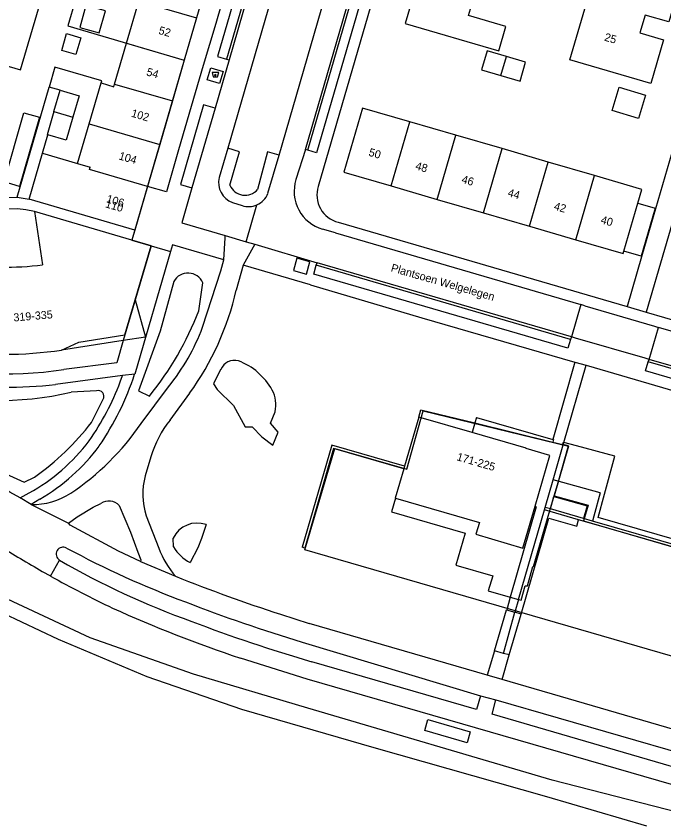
# Model space of a CAD drawing. Extents: x 194485 to 197793, y 468269 to 470822.
# Drawn here: x 194901 to 194998.1, y 469620.1 to 469740.5 of the extents above; entities that cross this region are included whole.
import ezdxf

# ---------------------------------------------------------------- set-up
doc = ezdxf.new("R2010")
doc.units = 0
for name, color, linetype in [('BGT begrenzing pand op maaiveld onder overbouw', 7, 'Continuous'), ('BGT grensvlak begroeid terreindeel', 7, 'Continuous'), ('BGT grensvlak begroeid terreindeel LR', 7, 'Continuous'), ('BGT grensvlak gebouwinstallatie plus 1', 7, 'Continuous'), ('BGT grensvlak onbegroeid terreindeel', 7, 'Continuous'), ('BGT grensvlak onbegroeid terreindeel LR', 7, 'Continuous'), ('BGT grensvlak ondersteunend wegdeel', 7, 'Continuous'), ('BGT grensvlak overig bouwwerk', 7, 'Continuous'), ('BGT grensvlak overig bouwwerk uitbreiding populatie', 7, 'Continuous'), ('BGT grensvlak pand deel overbouw', 7, 'Continuous'), ('BGT grensvlak pand min 1', 7, 'Continuous'), ('BGT grensvlak pand op maaiveld', 7, 'Continuous'), ('BGT grensvlak pand op maaiveld LR', 7, 'Continuous'), ('BGT grensvlak scheiding', 7, 'Continuous'), ('BGT grensvlak waterdeel', 7, 'Continuous'), ('BGT grensvlak wegdeel', 7, 'Continuous'), ('BGT puntobject bak afval apart plaats', 7, 'Continuous'), ('BGT tekst huisnummerreeks', 7, 'Continuous'), ('BGT tekst huisnummerreeks min 1', 7, 'Continuous'), ('BGT tekst openbare ruimte label weg', 7, 'Continuous')]:
    doc.layers.add(name, color=color, linetype=linetype)

msp = doc.modelspace()

# ---------------------------------------------------------------- linework, layer by layer
at = {"layer": 'BGT begrenzing pand op maaiveld onder overbouw'}
msp.add_line((194917.33, 469692.72), (194918.86, 469697.98), dxfattribs=at)
for points in [[(194907.85, 469690.46), (194910.41, 469691.65), (194917.33, 469692.72)], [(194969.35, 469678.09), (194961.73, 469680.3), (194961.73, 469680.28), (194961.34, 469680.39)], [(194978.76, 469667.05), (194980.96, 469674.66), (194977.41, 469675.69), (194977.42, 469675.75), (194969.35, 469678.09)], [(194957.86, 469668.27), (194970.42, 469664.64), (194969.89, 469662.85), (194976.95, 469660.79), (194978.76, 469667.05)]]:
    msp.add_lwpolyline(points, dxfattribs=at)
at = {"layer": 'BGT grensvlak begroeid terreindeel'}
for p, q in [((194928.38, 469696.35), (194929, 469700.54)), ((194913.06, 469684.35), (194909.3, 469684.14)), ((194912.33, 469679.62), (194914.05, 469683.08)), ((194924.63, 469660.97), (194924.55, 469662.26))]:
    msp.add_line(p, q, dxfattribs=at)
for points in [[(194924.66, 469700.75), (194922.59, 469693.27), (194919.34, 469684.37), (194921, 469683.57)], [(194931.67, 469687.54), (194930.59, 469685.41), (194931.17, 469684.54), (194933.58, 469682.13), (194935.32, 469678.95), (194936.4, 469678.95), (194937.82, 469677.44), (194939.49, 469676.21), (194940.3, 469678.14), (194939.15, 469679.49), (194939.82, 469681.21)], [(194880.81, 469682.3), (194889.88, 469677.07), (194897.14, 469672.94), (194902.24, 469670.67), (194903.78, 469671.41)], [(194929.49, 469664.31), (194928.78, 469662.22), (194928.23, 469660.82), (194927.09, 469658.65)]]:
    msp.add_lwpolyline(points, dxfattribs=at)
for centre, radius, start, end in [((194926.78, 469699.56), 2.43, 23.9013, 150.6072), ((194885.11, 469712.8), 46.29, 320.8368, 339.1911), ((194933.76, 469686.66), 2.26, 75.4097, 157.1488), ((194930.81, 469679.68), 9.82, 29.1576, 69.0085), ((194898.54, 469731.09), 48.17, 254.6702, 282.906), ((194913.32, 469683.53), 0.862, 328.322, 107.5462), ((194935.4, 469682.28), 4.54, 346.3659, 28.8095), ((194881.04, 469703.67), 39.47, 305.1859, 322.463), ((194928.16, 469660.55), 3.99, 70.4359, 154.6193), ((194929.58, 469663.75), 5.68, 209.3541, 244.023)]:
    msp.add_arc(centre, radius, start, end, dxfattribs=at)
at = {"layer": 'BGT grensvlak begroeid terreindeel LR'}
msp.add_lwpolyline([(195139.42, 469572.39), (195126.11, 469578.61), (195110.6, 469585.25), (195087.07, 469594.31), (195079.56, 469596.73), (195063.35, 469601.44), (195045.76, 469607.19), (195000.41, 469621.1), (194981.32, 469626.01), (194944.75, 469636.79), (194927.61, 469641.91), (194912.14, 469647.34), (194895.12, 469655.28), (194890.12, 469657.98)], dxfattribs=at)
at = {"layer": 'BGT grensvlak gebouwinstallatie plus 1'}
for p, q in [((194977.35, 469733.59), (194974.47, 469734.43)), ((194976.53, 469730.76), (194977.35, 469733.59)), ((194973.64, 469731.6), (194976.53, 469730.76)), ((194899.23, 469715.64), (194902.21, 469726.02)), ((194904.52, 469725.35), (194901.53, 469714.98)), ((194902.21, 469726.02), (194904.52, 469725.35)), ((194901.53, 469714.98), (194899.23, 469715.64))]:
    msp.add_line(p, q, dxfattribs=at)
for points in [[(194991.36, 469729.84), (194995.33, 469728.62), (194994.27, 469725.13), (194990.3, 469726.34), (194991.36, 469729.84)], [(194994.16, 469712.47), (194996.77, 469711.71), (194994.68, 469704.52), (194992.07, 469705.28)]]:
    msp.add_lwpolyline(points, dxfattribs=at)
at = {"layer": 'BGT grensvlak onbegroeid terreindeel'}
msp.add_lwpolyline([(194962.25, 469633.46), (194962.72, 469635.09), (194969.06, 469633.26), (194968.59, 469631.62), (194962.25, 469633.46)], dxfattribs=at)
at = {"layer": 'BGT grensvlak onbegroeid terreindeel LR'}
msp.add_lwpolyline([(194913.76, 469730.48), (194913.85, 469730.79), (194906.83, 469732.83), (194905.98, 469729.84)], dxfattribs=at)
at = {"layer": 'BGT grensvlak ondersteunend wegdeel'}
for points in [[(194933.05, 469715.15), (194934.51, 469720.17), (194932.73, 469720.69)], [(194940.41, 469719.68), (194938.67, 469720.14), (194937.19, 469714.51)]]:
    msp.add_lwpolyline(points, dxfattribs=at)
msp.add_arc((194935.32, 469716.11), 2.46, 202.9234, 319.4844, dxfattribs=at)
at = {"layer": 'BGT grensvlak overig bouwwerk'}
msp.add_lwpolyline([(194943.1, 469704.22), (194942.56, 469702.38), (194944.51, 469701.82), (194945.04, 469703.66), (194943.1, 469704.22)], dxfattribs=at)
at = {"layer": 'BGT grensvlak overig bouwwerk uitbreiding populatie'}
for p, q in [((194907.87, 469735.34), (194908.6, 469737.87)), ((194908.6, 469737.87), (194910.73, 469737.25)), ((194910.73, 469737.25), (194909.99, 469734.72)), ((194909.99, 469734.72), (194907.87, 469735.34)), ((194971.58, 469735.27), (194970.76, 469732.44)), ((194974.47, 469734.43), (194971.58, 469735.27)), ((194973.64, 469731.6), (194974.47, 469734.43)), ((194970.76, 469732.44), (194973.64, 469731.6))]:
    msp.add_line(p, q, dxfattribs=at)
at = {"layer": 'BGT grensvlak pand deel overbouw'}
for p, q in [((194917.08, 469691.9), (194907.85, 469690.46)), ((194969.76, 469679.53), (194981.43, 469676.68)), ((194981.43, 469676.68), (194982.91, 469676.32)), ((194980.98, 469666.41), (194982.21, 469670.63)), ((194975.06, 469653.44), (194976.3, 469653.09))]:
    msp.add_line(p, q, dxfattribs=at)
for points in [[(194918.86, 469697.98), (194920.4, 469692.41), (194917.08, 469691.9)], [(194961.34, 469680.39), (194961.65, 469681.5), (194969.76, 469679.53)], [(194982.21, 469670.63), (194983.8, 469676.1), (194982.91, 469676.32)], [(194957.86, 469668.27), (194957.28, 469666.24), (194968.29, 469663.02), (194966.89, 469658.25), (194972.42, 469656.64), (194971.76, 469654.39), (194975.06, 469653.44)], [(194976.3, 469653.09), (194976.69, 469652.98), (194977.3, 469655.15), (194977.62, 469655.14), (194978.45, 469658.05), (194978.55, 469658.03), (194980.98, 469666.41)]]:
    msp.add_lwpolyline(points, dxfattribs=at)
at = {"layer": 'BGT grensvlak pand min 1'}
for points in [[(194861.26, 469761.31), (194911.07, 469746.86), (194908.8, 469739.04), (194926.21, 469733.91), (194918.38, 469706.93), (194921.25, 469706.09), (194917.08, 469691.9), (194907.85, 469690.46)], [(195087.8, 469618.92), (195038.21, 469633.32), (194995.61, 469645.66), (194944.3, 469660.52), (194948.77, 469675.69), (194959.55, 469672.6), (194962, 469681.35), (194983.77, 469676.04), (194981.65, 469668.62), (194986.71, 469667.21), (194986.04, 469664.86), (195014.94, 469656.43), (195017.52, 469665.35), (195039.43, 469659.92), (195037.27, 469652.55), (195042.33, 469651.11), (195041.68, 469648.74), (195070.6, 469640.31), (195073.09, 469649.05), (195078.94, 469647.69), (195095.05, 469643.75)]]:
    msp.add_lwpolyline(points, dxfattribs=at)
msp.add_arc((194899.31, 469747.45), 57.63, 261.3794, 278.5138, dxfattribs=at)
at = {"layer": 'BGT grensvlak pand op maaiveld'}
for p, q in [((194929.88, 469746.52), (194928.06, 469740.23)), ((194917.58, 469736.45), (194919.4, 469742.74)), ((194928.06, 469740.23), (194926.22, 469733.9)), ((194915.79, 469730.29), (194917.58, 469736.45)), ((194926.22, 469733.9), (194924.44, 469727.78)), ((194911.98, 469724.35), (194913.76, 469730.48)), ((194906.68, 469726.19), (194907.61, 469729.37)), ((194924.44, 469727.78), (194922.55, 469721.27)), ((194910.24, 469718.4), (194911.98, 469724.35)), ((194966.91, 469722.64), (194960, 469724.65)), ((194973.83, 469720.63), (194966.91, 469722.64)), ((194922.55, 469721.27), (194920.72, 469714.98)), ((194980.74, 469718.61), (194973.83, 469720.63)), ((194902.97, 469713.05), (194904.98, 469719.96)), ((194904.98, 469719.96), (194910.24, 469718.4)), ((194987.66, 469716.6), (194980.74, 469718.61)), ((194920.72, 469714.98), (194918.82, 469708.43)), ((194957.2, 469715.05), (194964.12, 469713.03)), ((194918.82, 469708.43), (194902.97, 469713.05)), ((194964.12, 469713.03), (194971.03, 469711.02)), ((194992.07, 469705.28), (194994.16, 469712.47)), ((194918.38, 469706.93), (194903.78, 469711.21)), ((194903.78, 469711.21), (194904.99, 469703.24)), ((194971.03, 469711.02), (194977.94, 469709.01)), ((194977.94, 469709.01), (194984.86, 469706.99)), ((194921.25, 469706.09), (194918.38, 469706.93)), ((194918.86, 469697.98), (194921.25, 469706.09)), ((194961.34, 469680.39), (194959.2, 469673.04)), ((194959.09, 469672.65), (194957.82, 469668.28)), ((194959.2, 469673.04), (194959.09, 469672.65)), ((194957.82, 469668.28), (194957.86, 469668.27))]:
    msp.add_line(p, q, dxfattribs=at)
for points in [[(194962.21, 469749.37), (194959.63, 469750.12), (194958.07, 469744.74), (194960.64, 469743.99), (194959.3, 469739.39), (194973.32, 469735.31), (194974.38, 469738.95), (194968.81, 469740.57), (194970.57, 469746.63)], [(194997.94, 469749.87), (194997.16, 469747.2), (195000.69, 469746.16), (194998.79, 469739.62), (194995.26, 469740.65)], [(194876.66, 469744.98), (194881.75, 469743.52), (194880.36, 469738.67), (194901.71, 469732.43), (194905.05, 469743.85), (194904.65, 469743.98), (194905.93, 469748.35)], [(194995.26, 469740.65), (194994.48, 469737.97), (194998.01, 469736.94), (194996.11, 469730.41), (194984, 469733.94), (194986.74, 469743.33)], [(194911.49, 469742.09), (194910.56, 469738.78), (194913.48, 469737.96), (194914.4, 469741.27), (194911.49, 469742.09)], [(194913.76, 469730.48), (194915.68, 469729.91), (194915.79, 469730.29)], [(194907.61, 469729.37), (194910.48, 469728.54), (194909.55, 469725.34)], [(194906.68, 469726.19), (194905.67, 469722.71), (194905.77, 469722.68)], [(194960, 469724.65), (194952.9, 469726.72), (194950.1, 469717.11), (194957.2, 469715.05)], [(194909.55, 469725.34), (194908.55, 469721.88), (194905.77, 469722.68)], [(194994.16, 469712.47), (194994.76, 469714.53), (194987.66, 469716.6)], [(194984.86, 469706.99), (194991.97, 469704.92), (194992.07, 469705.28)]]:
    msp.add_lwpolyline(points, dxfattribs=at)
for centre, radius, start, end in [((194899.21, 469746.36), 43.5, 261.2075, 277.6404), ((194899.31, 469747.45), 57.63, 261.3794, 278.5138)]:
    msp.add_arc(centre, radius, start, end, dxfattribs=at)
at = {"layer": 'BGT grensvlak pand op maaiveld LR'}
for p, q in [((194919.4, 469742.74), (194928.06, 469740.23)), ((194917.58, 469736.45), (194926.22, 469733.9)), ((194915.79, 469730.29), (194924.44, 469727.78)), ((194906.68, 469726.19), (194909.55, 469725.34)), ((194911.98, 469724.35), (194922.55, 469721.27)), ((194957.2, 469715.05), (194960, 469724.65)), ((194964.12, 469713.03), (194966.91, 469722.64)), ((194971.03, 469711.02), (194973.83, 469720.63)), ((194910.24, 469718.4), (194912.12, 469717.86)), ((194977.94, 469709.01), (194980.74, 469718.61)), ((194984.86, 469706.99), (194987.66, 469716.6))]:
    msp.add_line(p, q, dxfattribs=at)
msp.add_lwpolyline([(194920.72, 469714.98), (194912.01, 469717.51), (194912.12, 469717.86)], dxfattribs=at)
at = {"layer": 'BGT grensvlak scheiding'}
for p, q in [((194948.31, 469676.2), (194943.87, 469660.9)), ((194959.2, 469673.04), (194948.31, 469676.2)), ((194959.09, 469672.65), (194948.59, 469675.7)), ((194980.17, 469666.5), (194980.28, 469666.89)), ((194985.29, 469665.02), (194980.17, 469666.5)), ((194981.06, 469666.66), (194980.28, 469666.89)), ((194986.02, 469665.23), (194981.06, 469666.66)), ((194987.24, 469664.46), (194985.29, 469665.02)), ((194987.35, 469664.84), (194986.02, 469665.23)), ((195014.81, 469656.91), (194987.35, 469664.84)), ((195014.7, 469656.52), (194987.24, 469664.46))]:
    msp.add_line(p, q, dxfattribs=at)
msp.add_lwpolyline([(194948.59, 469675.7), (194944.26, 469660.79), (194943.87, 469660.9)], dxfattribs=at)
at = {"layer": 'BGT grensvlak waterdeel'}
msp.add_lwpolyline([(194885.88, 469658.57), (194896.27, 469652.35), (194907.34, 469647.16), (194920.63, 469641.54), (194934.81, 469636.66), (194954.61, 469630.93), (194980.5, 469623.55), (194995.44, 469619.16)], dxfattribs=at)
msp.add_lwpolyline([(194885.88, 469658.57), (194896.27, 469652.35), (194907.34, 469647.16), (194920.63, 469641.54), (194934.81, 469636.66), (194954.61, 469630.93), (194980.5, 469623.55), (194995.44, 469619.16)], dxfattribs=at)
at = {"layer": 'BGT grensvlak wegdeel'}
for p, q in [((194952.98, 469804.59), (194932.54, 469734.04)), ((194953.37, 469804.48), (194932.92, 469733.93)), ((194944.37, 469720.5), (194967.4, 469800.33)), ((194944.75, 469720.39), (194967.78, 469800.2)), ((194945.29, 469763.92), (194932.73, 469720.69)), ((194940.41, 469719.68), (194952.48, 469761.2)), ((194959.7, 469761.2), (194946.29, 469714.97)), ((194932.92, 469733.93), (194930.85, 469726.69)), ((194932.54, 469734.04), (194932.92, 469733.93)), ((194901.17, 469713.34), (194905.98, 469729.84)), ((194907.61, 469729.37), (194905.98, 469729.84)), ((194930.85, 469726.69), (194927.35, 469714.76)), ((195004.21, 469726.35), (194995.41, 469696.13)), ((194904.98, 469719.96), (194905.77, 469722.68)), ((194932.73, 469720.69), (194931.46, 469716.31)), ((194944.37, 469720.5), (194942.95, 469715.99)), ((194944.75, 469720.39), (194944.37, 469720.5)), ((194938.74, 469713.94), (194940.41, 469719.68)), ((194925.65, 469715.26), (194927.35, 469714.76)), ((194927.35, 469714.76), (194927.05, 469713.73)), ((194901.17, 469713.34), (194902.97, 469713.05)), ((194927.05, 469713.73), (194925.85, 469709.5)), ((194933.46, 469712.56), (194934.89, 469712.11)), ((194935.49, 469706.68), (194937.11, 469712.21)), ((194925.85, 469709.5), (194932.35, 469707.6)), ((194949.26, 469709.61), (194992.54, 469696.99)), ((194918.82, 469708.43), (194918.38, 469706.93)), ((194948.85, 469708), (194946.93, 469708.56)), ((194932.35, 469707.6), (194935.49, 469706.68)), ((194948.85, 469708), (194985.61, 469697.27)), ((194921.25, 469706.09), (194924.18, 469705.23)), ((194936.8, 469706.3), (194935.05, 469703.16)), ((194935.49, 469706.68), (194936.8, 469706.3)), ((194936.8, 469706.3), (194946.11, 469703.54)), ((194924.18, 469705.23), (194918.79, 469686.86)), ((194946, 469703.16), (194946.11, 469703.54)), ((194984.21, 469692.45), (194946.11, 469703.54)), ((194935.05, 469703.16), (194934.01, 469699.43)), ((194945.11, 469700.24), (194935.05, 469703.16)), ((194984.09, 469692.06), (194946, 469703.16)), ((194945.11, 469700.24), (194961.83, 469695.28)), ((194985.61, 469697.27), (194984.21, 469692.45)), ((194986.23, 469697.09), (194985.61, 469697.27)), ((194992.54, 469696.99), (194995.41, 469696.13)), ((194995.41, 469696.13), (195040.65, 469682.93)), ((194961.83, 469695.28), (194984.74, 469688.64)), ((194995.84, 469689.06), (194997.25, 469693.86)), ((195040.04, 469681.38), (194997.25, 469693.86)), ((194917.33, 469692.72), (194917.08, 469691.9)), ((194984.21, 469692.45), (194984.09, 469692.06)), ((194984.81, 469692.26), (194984.21, 469692.45)), ((194995.24, 469689.23), (194984.81, 469692.26)), ((194995.84, 469689.06), (194995.24, 469689.23)), ((194995.73, 469688.68), (194995.84, 469689.06)), ((195038.68, 469676.55), (194995.84, 469689.06)), ((194984.74, 469688.64), (194981.44, 469677.08)), ((194983.08, 469676.61), (194986.4, 469688.21)), ((194984.74, 469688.64), (194986.4, 469688.21)), ((195038.57, 469676.17), (194995.73, 469688.68)), ((194916.98, 469686.62), (194906.95, 469685.29)), ((194916.64, 469685.68), (194916.98, 469686.62)), ((194918.79, 469686.86), (194916.98, 469686.62)), ((194919.76, 469679.46), (194923.88, 469684.95)), ((194927.02, 469683.98), (194924.08, 469679.97)), ((194969.76, 469679.53), (194969.35, 469678.09)), ((194969.99, 469680.33), (194969.76, 469679.53)), ((194969.99, 469680.33), (194981.44, 469677.08)), ((194981.46, 469671.01), (194983.08, 469676.61)), ((194984.96, 469676.1), (194983.08, 469676.61)), ((194921.2, 469674.48), (194920.36, 469671.63)), ((194980.28, 469666.89), (194981.46, 469671.01)), ((194988.53, 469669.04), (194981.46, 469671.01)), ((194901.65, 469668.33), (194902.98, 469669.05)), ((194981.06, 469666.66), (194981.6, 469668.53)), ((194988.53, 469669.04), (194987.56, 469665.55)), ((194988.2, 469665.36), (194989.16, 469668.87)), ((194903.29, 469667.3), (194901.65, 469668.33)), ((194904.58, 469668.12), (194903.29, 469667.3)), ((194903.29, 469667.3), (194908.87, 469664.5)), ((194976.3, 469653.09), (194980.17, 469666.5)), ((194920.51, 469665.63), (194922.4, 469660.77)), ((194987.56, 469665.55), (194987.35, 469664.84)), ((194906.17, 469656.6), (194907.53, 469658.97)), ((194919.64, 469658.77), (194924.89, 469656.57)), ((194976.3, 469653.09), (194975.75, 469651.17)), ((194972.69, 469645.39), (194974.51, 469651.52)), ((194974.51, 469651.52), (194975.75, 469651.17)), ((194940.62, 469650.87), (194944.92, 469649.5)), ((194974.02, 469645.01), (194975.75, 469651.17)), ((194974.89, 469644.77), (194976.69, 469650.89)), ((194976.69, 469650.89), (194975.75, 469651.17)), ((194971.6, 469641.74), (194944.92, 469649.5)), ((194943.88, 469646.68), (194970.6, 469638.66)), ((194972.69, 469645.39), (194971.6, 469641.74)), ((194974.02, 469645.01), (194972.69, 469645.39)), ((194973.82, 469641.09), (194974.89, 469644.77)), ((194974.89, 469644.77), (194974.02, 469645.01)), ((194973.82, 469641.09), (194971.6, 469641.74)), ((195027.29, 469625.55), (194973.82, 469641.09)), ((194970.6, 469638.66), (194972.88, 469638.07)), ((194972.88, 469638.07), (195026.41, 469622.61))]:
    msp.add_line(p, q, dxfattribs=at)
for points in [[(194949.39, 469803.2), (194947.37, 469796.09), (194943.72, 469783.51), (194941.9, 469777.22), (194938.23, 469764.55), (194936.4, 469758.26), (194934.58, 469751.97), (194932.76, 469745.68), (194930.93, 469739.39), (194929.03, 469733.07), (194927.26, 469726.96), (194925.37, 469720.45), (194923.54, 469714.16), (194920.72, 469714.98)], [(194940.09, 469765.02), (194931.22, 469734.44), (194932.54, 469734.04)], [(194903.78, 469711.21), (194902.47, 469711.48), (194901.22, 469711.62), (194897.76, 469711.56), (194893.52, 469711.92), (194889.88, 469712.63), (194884.67, 469714.21), (194880.58, 469716.22), (194878.32, 469717.66), (194874.58, 469720.68), (194872.77, 469722.45), (194869.85, 469725.3), (194867.11, 469729.04), (194864.88, 469732.74), (194863.37, 469736.08), (194862.32, 469739.59), (194861.49, 469742.61), (194861.06, 469744.92), (194860.8, 469749.01), (194860.21, 469752.8), (194859.41, 469756.09), (194858.65, 469759.44), (194857.92, 469762.67), (194858.76, 469762.96)], [(194958, 469761.2), (194946.04, 469720.02), (194944.75, 469720.39)], [(194868.56, 469759.19), (194862.71, 469760.89), (194860.13, 469760.25), (194861.88, 469753.13), (194862.48, 469749.19), (194862.74, 469745.13), (194863.14, 469742.99), (194863.94, 469740.06), (194864.96, 469736.67), (194866.38, 469733.53), (194868.52, 469729.97), (194871.13, 469726.41), (194875.71, 469721.95), (194879.32, 469719.04), (194881.41, 469717.69), (194885.29, 469715.79), (194890.29, 469714.28), (194893.75, 469713.6), (194897.82, 469713.26), (194901.17, 469713.34)], [(194929.65, 469730.93), (194930.2, 469732.73), (194932.06, 469732.17), (194931.51, 469730.37), (194929.65, 469730.93)], [(194930.85, 469726.69), (194929.11, 469727.21), (194925.65, 469715.26)], [(195001.33, 469727.19), (194994.71, 469704.41), (194992.54, 469696.99)], [(194932.15, 469703.99), (194932.35, 469707.29), (194932.35, 469707.6)], [(194932.15, 469703.99), (194924.47, 469706.2), (194924.18, 469705.23)], [(194928.97, 469693.91), (194931.72, 469702.35), (194932.15, 469703.99)], [(194984.09, 469692.06), (194983.67, 469690.73), (194945.63, 469701.82), (194946, 469703.16)], [(194986.23, 469697.09), (194996.64, 469694.05), (194997.25, 469693.86)], [(194917.08, 469691.9), (194916.1, 469688.55), (194908.17, 469687.53)], [(194986.4, 469688.21), (195040.33, 469672.41), (195037.02, 469660.92)], [(195038.57, 469676.17), (195038.18, 469674.83), (194995.33, 469687.34), (194995.73, 469688.68)], [(194901.65, 469668.33), (194900.09, 469669.17), (194883.99, 469679.13), (194881.26, 469680.92)], [(194981.44, 469677.08), (194981.53, 469677.06), (194981.43, 469676.68)], [(194982.91, 469676.32), (194983, 469676.63), (194983.08, 469676.61)], [(194989.16, 469668.87), (194990.7, 469674.55), (194984.96, 469676.1)], [(194981.6, 469668.53), (194986.59, 469667.14), (194986.02, 469665.23)], [(194908.87, 469664.5), (194910.19, 469665.46), (194912.58, 469666.9), (194913.72, 469667.48)], [(194916.49, 469667.16), (194918.14, 469663.17), (194919.25, 469660.16), (194919.69, 469659.04), (194919.64, 469658.77)], [(194978.76, 469667.05), (194978.94, 469666.99), (194975.06, 469653.44)], [(195025.58, 469664.25), (195016.64, 469666.85), (195014.05, 469657.9), (195000, 469661.96), (194988.2, 469665.36)], [(194976.69, 469650.89), (194980.85, 469665.29), (194985.02, 469664.08), (194985.29, 469665.02)], [(194919.64, 469658.77), (194916.36, 469660.35), (194909.15, 469664.23), (194908.87, 469664.5)], [(194975.06, 469653.44), (194974.52, 469651.54), (194974.51, 469651.52)], [(195085.72, 469600.33), (194944.63, 469641.16), (194934.64, 469644.31)], [(194970.6, 469638.66), (194970.01, 469636.59), (194945.34, 469643.76)], [(195026.41, 469622.61), (195025.74, 469620.33), (194972.33, 469635.89), (194972.88, 469638.07)]]:
    msp.add_lwpolyline(points, dxfattribs=at)
for centre, radius, start, end in [((194934.5, 469715.52), 3.14, 165.411, 250.6817), ((194948.58, 469714.23), 5.9, 162.5914, 253.7255), ((194950.3, 469713.69), 4.21, 162.3329, 255.7745), ((194935.9, 469714.97), 3.02, 293.6117, 339.9362), ((194935.87, 469715.04), 3.09, 251.3942, 293.5492), ((194892.61, 469708.85), 42.45, 324.1396, 347.1827), ((194898.6, 469705.23), 32.41, 321.2622, 339.5502), ((194899.2, 469750.69), 63.8, 256.134, 278.0854), ((194878.69, 469699.92), 42.17, 325.5808, 341.9629), ((194899.56, 469753.5), 68.6, 263.0824, 276.1857), ((194879.07, 469699.93), 40.18, 324.957, 339.2275), ((194887.43, 469701.55), 39.16, 303.7998, 325.6543), ((194937.83, 469669.25), 17.43, 142.0685, 162.5342), ((194889.37, 469693.8), 28.24, 298.8023, 323.1405), ((194889.95, 469693.41), 29.22, 300.0423, 323.624), ((194930.25, 469668.86), 10.26, 164.3617, 198.3507), ((194903.42, 469677.95), 10.65, 269.3137, 302.9576), ((194914.92, 469665.69), 2.15, 43.1192, 123.8868), ((194981.41, 469791.02), 154.04, 237.963, 240.7623), ((194908.08, 469659.88), 1.05, 60.5846, 238.8947), ((194976.02, 469785.72), 141.96, 241.6428, 249.5348), ((194935.84, 469665.91), 14.39, 200.9092, 220.4594), ((194968.89, 469765.55), 122.98, 240.0719, 250.2475), ((194980.4, 469789.19), 151.96, 240.7555, 244.7126), ((195020.68, 469896.27), 258.13, 248.2165, 251.9308), ((195014.69, 469880.2), 244.01, 248.7848, 253.1313), ((194999.46, 469838.28), 204.52, 245.7586, 251.5196), ((195009.51, 469864.59), 229.97, 249.0617, 253.7977)]:
    msp.add_arc(centre, radius, start, end, dxfattribs=at)
at = {"layer": 'BGT puntobject bak afval apart plaats'}
msp.add_lwpolyline([(194931.21, 469731.37), (194931.38, 469732.04), (194930.38, 469732.04), (194930.55, 469731.37)], close=True, dxfattribs=at)
msp.add_circle((194930.88, 469731.64), 0.1, dxfattribs=at)
for start, end in [(0, 180), (180, 0)]:
    msp.add_arc((194930.88, 469731.64), 0.1, start, end, dxfattribs=at)

# ---------------------------------------------------------------- texts
at = {"layer": 'BGT tekst huisnummerreeks'}
for s, rotation, p in [('52', 343.8, (194922.28, 469737.85)), ('25', 343.7, (194989.05, 469736.84)), ('54', 343.8, (194920.46, 469731.63)), ('102', 343.8, (194918.18, 469725.44)), ('50', 343.8, (194953.75, 469719.59)), ('104', 343.8, (194916.32, 469719.04)), ('48', 343.8, (194960.75, 469717.55)), ('46', 343.8, (194967.67, 469715.54)), ('44', 343.8, (194974.58, 469713.53)), ('106', 343.8, (194914.45, 469712.62)), ('42', 343.8, (194981.5, 469711.51)), ('40', 343.8, (194988.51, 469709.47)), ('319-335', 4.8, (194900.68, 469694.73)), ('171-225', 343.7, (194966.94, 469673.97))]:
    msp.add_text(s, height=1.2, rotation=rotation, dxfattribs=at).set_placement(p)
at = {"layer": 'BGT tekst huisnummerreeks min 1'}
msp.add_text('110', height=1.2, rotation=343.8, dxfattribs=at).set_placement((194914.3, 469711.86))
at = {"layer": 'BGT tekst openbare ruimte label weg'}
msp.add_text('Plantsoen Welgelegen', height=1.2, rotation=343.9, dxfattribs=at).set_placement((194957.08, 469702.27))

doc.saveas('drawing.dxf')
